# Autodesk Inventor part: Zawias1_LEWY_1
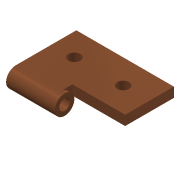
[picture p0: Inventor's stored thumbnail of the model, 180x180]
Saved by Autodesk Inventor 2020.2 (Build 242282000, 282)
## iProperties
Created: 2005-09
Part Number: Zawias1_LEWY_1
Document SubType Name: Modeling
Designer: F.Stasiak
Density: 1 g/cm^3
Material: Ogólny
Appearance: Miedziany (stary/polerowany)
Manager: www.cadconsulting.pl
Company: Fabian Stasiak CAD Consulting
Author: F.Stasiak
Subject: Zbiór ćwiczeń. Autodesk Inventor 2020. Kurs podstawowy
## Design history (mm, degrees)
derived "Zawias1.ipt"
  sketch "Szkic1"
    geometry: L1 (2, -31)-(25, -31) reference; L2 (25, -31)-(25, 0) reference; L3 (25, 0)-(-25, 0) reference; L4 (-25, 0)-(-25, -25) reference; L5 (-25, -25)-(2, -25) reference; L6 (2, -25)-(2, -31) reference; 2 further points
  sketch "Szkic2"
    geometry: L1 (5, 6)-(5, 0) reference; L2 (0, 6)-(0, 0) reference; C1 r 5 at (5, 0) reference
  sketch "Szkic4"
    geometry: L1 (-25, 0)-(-25, -25) reference; L2 (25, -26)-(25, 0) reference; L3 (-25, -12.5)-(25, -12.5) reference; L4 (-25, -25)-(2, -25) reference; L5 (25, -26)-(2, -26) reference; L6 (-11.5, -25)-(-11.5, -12.5) reference; L7 (13.5, -26)-(13.5, -12.5) reference
  sketch "Szkic5"
    geometry: C1 r 5 at (5, 0) reference; 3 further points
    constraints: 1 other
  sketch "Szkic6"
    geometry: C1 r 5 at (0, 0) reference
node "Bryła1"
node "Korpusy bryłowe"
node "Korpusy powierzchniowe"
tag "Bryła wyprowadzona2"
feature "Bryła1::Zawias1.ipt"
